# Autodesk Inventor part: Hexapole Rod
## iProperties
Shininess: 64.0
Length Units: 11272
Angle Units: 11279
Time Units: 11290
Mass Units: 11286
Length Display Precision: 3
Angle Display Precision: 2
Compacted: True
Part Number: Hexapole Rod
Document SubType Name: Modeling
Created: 2003-08
Designer: FT User
Manufacturer: Standard
Standards Organization: Custom
Density: 0.0
Volumn: 0.0
Area: 0.0
PropertySet Name: Model Information
Control State: 0
Master: False
Checked Out: False
Author: FT User
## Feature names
1. Extrusion1
